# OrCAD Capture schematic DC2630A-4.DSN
size Custom; title: I²C PROGRAMMABLE BOOST; rev: 4; note: DC2630A
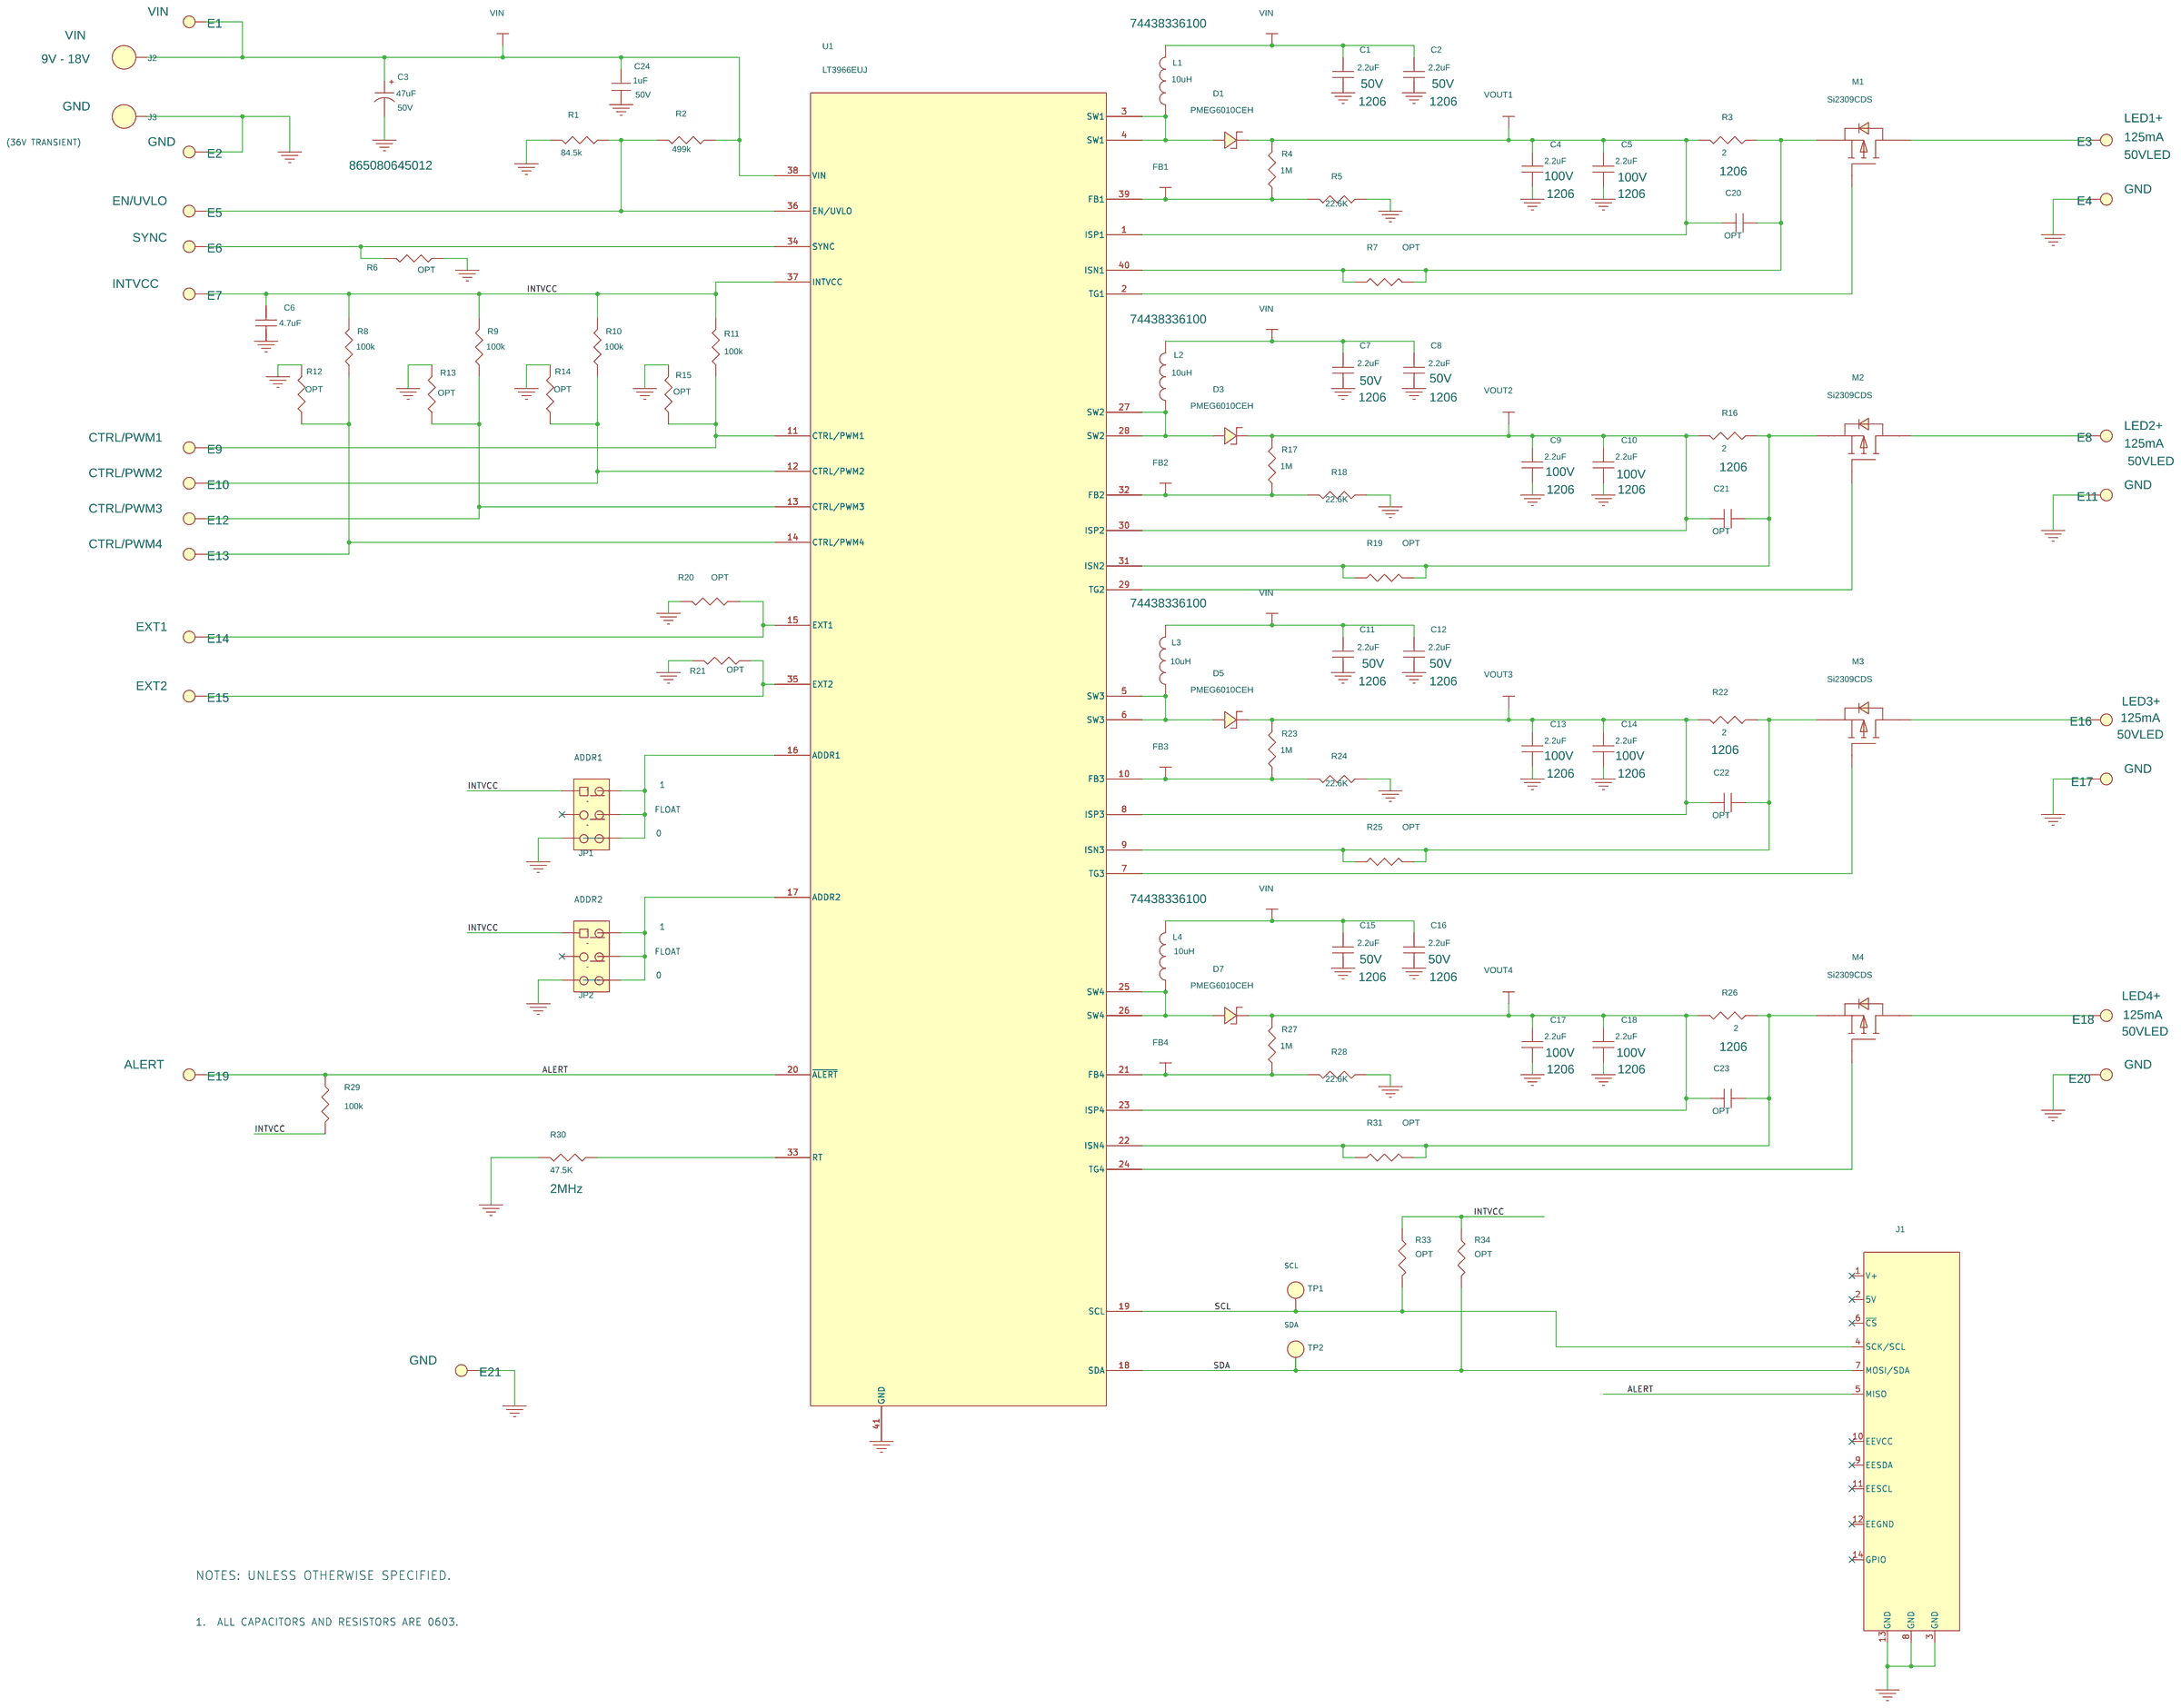
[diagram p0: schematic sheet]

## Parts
C1  2.2uF  [1206]
C2  2.2uF  [1206]
C3  47uF  [CAP-CE-BS-6.3X7.7]
C4  2.2uF  [1206]
C5  2.2uF  [1206]
C6  4.7uF  [0603]
C7  2.2uF  [1206]
C8  2.2uF  [1206]
C9  2.2uF  [1206]
C10  2.2uF  [1206]
C11  2.2uF  [1206]
C12  2.2uF  [1206]
C13  2.2uF  [1206]
C14  2.2uF  [1206]
C15  2.2uF  [1206]
C16  2.2uF  [1206]
C17  2.2uF  [1206]
C18  2.2uF  [1206]
C20  OPT  [0603]
C21  OPT  [0603]
C22  OPT  [0603]
C23  OPT  [0603]
C24  1uF  [0603]
D1  PMEG6010CEH  [SOD-123]
D3  PMEG6010CEH  [SOD-123]
D5  PMEG6010CEH  [SOD-123]
D7  PMEG6010CEH  [SOD-123]
E1  VIN  [MM/2308]
E2  GND  [MM/2308]
E3  LED1+  [MM/2501]
E4  GND  [MM/2501]
E5  EN/UVLO  [MM/2308]
E6  SYNC  [MM/2308]
E7  INTVCC  [MM/2308]
E8  LED2+  [MM/2501]
E9  CTRL/PWM1  [MM/2308]
E10  CTRL/PWM2  [MM/2308]
E11  GND  [MM/2501]
E12  CTRL/PWM3  [MM/2308]
E13  CTRL/PWM4  [MM/2308]
E14  EXT1  [MM/2308]
E15  EXT2  [MM/2308]
E16  LED3+  [MM/2501]
E17  GND  [MM/2501]
E18  LED4+  [MM/2501]
E19  ALERT  [MM/2308]
E20  GND  [MM/2501]
E21  GND  [MM/2308]
J1  2X7 RIBBON CONN.  [HD2X7-079-MOLEX]
J2  BANANA-JACK  [KEY-575-4]
J3  BANANA-JACK  [KEY-575-4]
JP1  JP2X3/079  [JP2X3/079]
JP2  JP2X3/079  [JP2X3/079]
L1  10uH  [IND-74438336100]
L2  10uH  [IND-74438336100]
L3  10uH  [IND-74438336100]
L4  10uH  [IND-74438336100]
M1  Si2309CDS  [SOT23]
M2  Si2309CDS  [SOT23]
M3  Si2309CDS  [SOT23]
M4  Si2309CDS  [SOT23]
R1  84.5k  [0603]
R2  499k  [0603]
R3  2  [1206]
R4  1M  [0603]
R5  22.6K  [0603]
R6  OPT  [0603]
R7  OPT  [0603]
R8  100k  [0603]
R9  100k  [0603]
R10  100k  [0603]
R11  100k  [0603]
R12  OPT  [0603]
R13  OPT  [0603]
R14  OPT  [0603]
R15  OPT  [0603]
R16  2  [1206]
R17  1M  [0603]
R18  22.6K  [0603]
R19  OPT  [0603]
R20  OPT  [0603]
R21  OPT  [0603]
R22  2  [1206]
R23  1M  [0603]
R24  22.6K  [0603]
R25  OPT  [0603]
R26  2  [1206]
R27  1M  [0603]
R28  22.6K  [0603]
R29  100k  [0603]
R30  47.5K  [0603]
R31  OPT  [0603]
R33  OPT  [0603]
R34  OPT  [0603]
TP1  TEST PAD  [TEST-PIN]
TP2  TEST PAD  [TEST-PIN]
U1  LT3966EUJ  [QFN(40)(UJ)6MMX6MM]

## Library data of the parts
C1 C2 C7 C8 C11 C12 C15 C16 = CAP_NP: 3RD PART FIELD: 50V
C3 = CAP+: 1ST PART FIELD: 50V; 2nd Part Field: 865080645012
C4 C5 C9 C10 C13 C14 C17 C18 = CAP_NP: 3RD PART FIELD: 100V
C6 = CAP_NP: 3rd Part Field: 16V
C20-C23 = CAP0603
C24 = CAP0603: 1ST PART FIELD: 50V
D1 D3 D5 D7 = B230A_0: 4th Part Field: NXP
E1 E2 E4-E7 E9-E15 E17 E19-E21 = T_POINT_R: v: 2.8V- 16V
E3 E8 E16 E18 = T_POINT_R: 1ST PART FIELD: 125mA; OUTPUT: 50VLED; v: 2.8V- 16V
J1 = CONN,_2X7__0.079_MOLEX_RIBBON
J2 = BANANA-JACK: 4th Part Field: VIN; VALUE1: 9V - 18V
J3 = BANANA-JACK: 4th Part Field: GND
JP1 JP2 = JP2X3_079
L1-L4 = INDUCTOR: MANU#: 74438336100
M1-M4 = SI2303BDS_1
R1-R6 R8-R18 R20-R24 R26-R29 = R
R7 R19 R25 R31 = AAC-0402
R30 = R: 1ST PART FIELD: 2MHz
R33 R34 = AAC-0603
TP1 TP2 = TEST_PAD_COPPER_FEATURE_0
U1 = LT3966_14

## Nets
GND: C1.2 C2.2 C3.2 C4.2 C5.2 C6.2 C7.2 C8.2 C9.2 C10.2 C11.2 C12.2 C13.2 C14.2 C15.2 C16.2 C17.2 C18.2 C24.2 E2.1(TP) E4.1(TP) E11.1(TP) E17.1(TP) E20.1(TP) E21.1(TP) J1.3(GND) J1.8(GND) J1.13(GND) J3.1 JP1.5 JP2.5 R1.2 R5.1 R6.1 R12.2 R13.2 R14.2 R15.2 R18.1 R20.2 R21.2 R24.1 R28.1 R30.2 U1.41(GND)
VIN: C1.1 C2.1 C3.1 C7.1 C8.1 C11.1 C12.1 C15.1 C16.1 C24.1 E1.1(TP) J2.1 L1.2 L2.2 L3.2 L4.2 R2.1 U1.38(VIN)
ALERT: E19.1(TP) J1.5(MISO) R29.1 U1.20(~{ALERT})
FB1: R4.1 R5.2 U1.39(FB1)
FB2: R17.1 R18.2 U1.32(FB2)
FB3: R23.1 R24.2 U1.10(FB3)
FB4: R27.1 R28.2 U1.21(FB4)
INTVCC: C6.1 E7.1(TP) JP1.1 JP2.1 R8.2 R9.2 R10.2 R11.2 R29.2 R33.1 R34.1 U1.37(INTVCC)
SCL: J1.4(SCK/SCL) R33.2 TP1.1(P1) U1.19(SCL)
SDA: J1.7(MOSI/SDA) R34.2 TP2.1(P1) U1.18(SDA)
VOUT1: C4.1 C5.1 C20.1 D1.1(CATHODE) R3.2 R4.2 U1.1(ISP1)
VOUT2: C9.1 C10.1 C21.1 D3.1(CATHODE) R16.2 R17.2 U1.30(ISP2)
VOUT3: C13.1 C14.1 C22.1 D5.1(CATHODE) R22.2 R23.2 U1.8(ISP3)
VOUT4: C17.1 C18.1 C23.1 D7.1(CATHODE) R26.2 R27.2 U1.23(ISP4)
N16898168: E9.1(TP) R11.1 R15.1 U1.11(CTRL/PWM1)
N16898482: E10.1(TP) R10.1 R14.1 U1.12(CTRL/PWM2)
N16898800: E12.1(TP) R9.1 R13.1 U1.13(CTRL/PWM3)
N16899183: E13.1(TP) R8.1 R12.1 U1.14(CTRL/PWM4)
N16900510: E14.1(TP) R20.1 U1.15(EXT1)
N16900722: E15.1(TP) R21.1 U1.35(EXT2)
N16900851: E6.1(TP) R6.2 U1.34(SYNC)
N16901062: E5.1(TP) R1.1 R2.2 U1.36(EN/UVLO)
N16923405: R30.1 U1.33(RT)
N16929705: M1.1 U1.2(TG1)
N16929707: C20.2 M1.2 R3.1 R7.1 R7.2 U1.40(ISN1)
N16929752: D1.2(ANODE) L1.1 U1.3(SW1) U1.4(SW1)
N16930821: E3.1(TP) M1.3
N16979651: E8.1(TP) M2.3
N16979677: C21.2 M2.2 R16.1 R19.1 R19.2 U1.31(ISN2)
N16979944: M2.1 U1.29(TG2)
N16979967: D3.2(ANODE) L2.1 U1.27(SW2) U1.28(SW2)
N16981665: E16.1(TP) M3.3
N16981681: C22.2 M3.2 R22.1 R25.1 R25.2 U1.9(ISN3)
N16981956: M3.1 U1.7(TG3)
N16981979: D5.2(ANODE) L3.1 U1.5(SW3) U1.6(SW3)
N16982751: E18.1(TP) M4.3
N16982767: C23.2 M4.2 R26.1 R31.1 R31.2 U1.22(ISN4)
N16983042: M4.1 U1.24(TG4)
N16983065: D7.2(ANODE) L4.1 U1.25(SW4) U1.26(SW4)
N16996199: JP1.2 JP1.4 JP1.6 U1.16(ADDR1)
N16996293: JP2.2 JP2.4 JP2.6 U1.17(ADDR2)

Not connected (* = marked no-connect by the designer): J1 1(V+)* 2(5V)* 6(~{CS})* 9(EESDA)* 10(EEVCC)* 11(EESCL)* 12(EEGND)* 14(GPIO)*; JP1 3*; JP2 3*

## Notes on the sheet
- (36V TRANSIENT)
- ADDR1
- 1
- FLOAT
- 0
- ADDR2
- 1
- FLOAT
- 0
- SCL
- SDA
- NOTES: UNLESS OTHERWISE SPECIFIED.
- 1.  ALL CAPACITORS AND RESISTORS ARE 0603.
